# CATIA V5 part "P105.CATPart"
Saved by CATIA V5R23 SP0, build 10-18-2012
Part number: P105
Definition: Vis Chc M5x50
Description: ISO 4762 Vis Chc M5x50
Publications: "Mating Edge", "Axis"
Bounding box of the stored display mesh (mm): x -50 to 5, y -4.25 to 4.25, z -4.207 to 4.207
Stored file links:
  C:\wamp\www\COURS\CONCEPTION GMP1\TITRE 02-SEMESTRE 2\03-TP7-PRESSE MECANIQUE\eleve\P105.CATPart
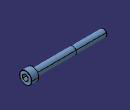
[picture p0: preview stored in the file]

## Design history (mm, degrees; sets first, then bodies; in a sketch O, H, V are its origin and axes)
Parameters
  Material = "St"
  d_dia = 5 mm
  l_nom = 50 mm
  k_head_depth_max = 5 mm
  s_nom = 4 mm
  r_min = 0.2 mm
  ds_max = 5 mm
  e = 4.58 mm
  t_min = 2.5 mm
  p_pitch = 0.8 mm
  Threading = 22 mm
  dk_max = 8.5 mm
  PartNumber = "ISO 4762 Vis Chc M5x50"
Body1 "PartBody" (main body)
  Sketch1 on yz-plane, origin (0, 0, 0), H (0, 1, 0), V (0, 0, 1)
    circle A1 centre (0, 0) radius 4.25
    radius A1 = 4.25 {= dk_max /2}
  Pad1: profile Sketch1, direction (1, 0, 0), length 5 {= k_head_depth_max}
  Fillet1: radius 0.2 {= r_min}, on edge [face of Pad1 | face of Pad1]
  Body2
    Sketch2 on face of Pad1, origin (5, 0, 0), H (0, 1, 0), V (0, 0, 1)
      point P1 (2, -1.1547)
      point P2 (2, 1.1547)
      point P3 (0, 2.3094)
      point P4 (-2, 1.1547)
      point P5 (-2, -1.1547)
      point P6 (0, -2.3094)
      point P7 (2, 0)
      line L1 (2, -1.1547) -> (2, 1.1547)
      line L2 (2, 1.1547) -> (0, 2.3094)
      line L3 (0, 2.3094) -> (-2, 1.1547)
      line L4 (-2, 1.1547) -> (-2, -1.1547)
      line L5 (-2, -1.1547) -> (0, -2.3094)
      line L6 (0, -2.3094) -> (2, -1.1547)
      construction line L7 (0, 0) -> (2, 0)
      construction circle A1 centre (0, 0) radius 2.3094
      construction arc A2 centre (-2, -1.1547) radius 2.3094 from (-2, 1.1547) to (0, -2.3094) cw
      construction arc A3 centre (2, 1.1547) radius 2.3094 from (0, 2.3094) to (2, -1.1547) ccw
      point P8 (-2, -1.1547)
      point P9 (2, 1.1547)
      distance L1 L4 = 4 {= s_nom}
      horizontal: L7 H
      coincidence: A1 P1, A1 P2, A1 P3, A1 P4, A1 P5, A1 P6, A2 P4, A2 P6, A2 O, P8 P5, A3 P3, A3 P1, A3 O, P9 P2
      midpoint: P7 L1
    Pad2: profile Sketch2, direction (-1, 0, 0), length 3.8199 {= t_min +(e /3.47)}
    Body3
      Sketch3 on zx-plane, origin (0, 0, 0), H (-1, 0, 0), V (0, 0, 1)
        point P1 (-1.1779, 0)
        line L1 (-1.1779, 0) -> (-2.5, 2.29)
        line L2 (-2.5, 2.29) -> (-5, 2.29)
        line L3 (-5, 2.29) -> (-5, 0)
        axis line L4 (-46.2384, 0) -> (26.3409, 0)
        reference projected line E1 (-5, -6.9227) -> (-5, 6.9227) from edge [face of Pad2 | face of Pad2]
        length L2 = 2.5 {= t_min}
        angle L1 L4 = 60
        distance L2 L4 = 2.29 {= e /2}
        horizontal: L2 H, L4 H
        perpendicularity: L3 L2
        fix: L4
        coincidence: L3 E1, P1 L4
      Shaft1: profile Sketch3, axis Sketch3.L4, angle 360
    Intersect1: tool Body3
  Remove1: tool Body2
  Sketch4 on xy-plane, origin (0, 0, 0), H (1, 0, 0), V (0, 1, 0)
    line L1 (0, 0) -> (0, 2.5)
    line L2 (0, 2.5) -> (-28, 2.5)
    line L3 (-28, 2.5) -> (-28, 2.439)
    line L4 (-28, 2.439) -> (-50, 2.439)
    line L5 (-50, 2.439) -> (-50, 0)
    axis line L6 (-192.3446, 0) -> (99.1594, 0)
    distance L5 L1 = 50 {= l_nom}
    distance L3 L5 = 22 {= Threading}
    distance L2 L6 = 2.5 {= ds_max /2}
    distance L4 L6 = 2.439 {= d_dia /2.05}
    vertical: L1 V, L3 V, L5 V
    horizontal: L2 H, L4 H, L6 H
    fix: L6
  Shaft2: profile Sketch4, axis Sketch4.L6, angle 360
  Fillet2: radius 0.2 {= r_min}, on edge [face of Shaft2 | face of Pad1]
  Chamfer1: length 0.8 {= p_pitch}, angle 45, on edge [face of Shaft2 | face of Shaft2]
